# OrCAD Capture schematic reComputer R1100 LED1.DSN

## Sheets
1 02 LED: size A3; rev: v1.0
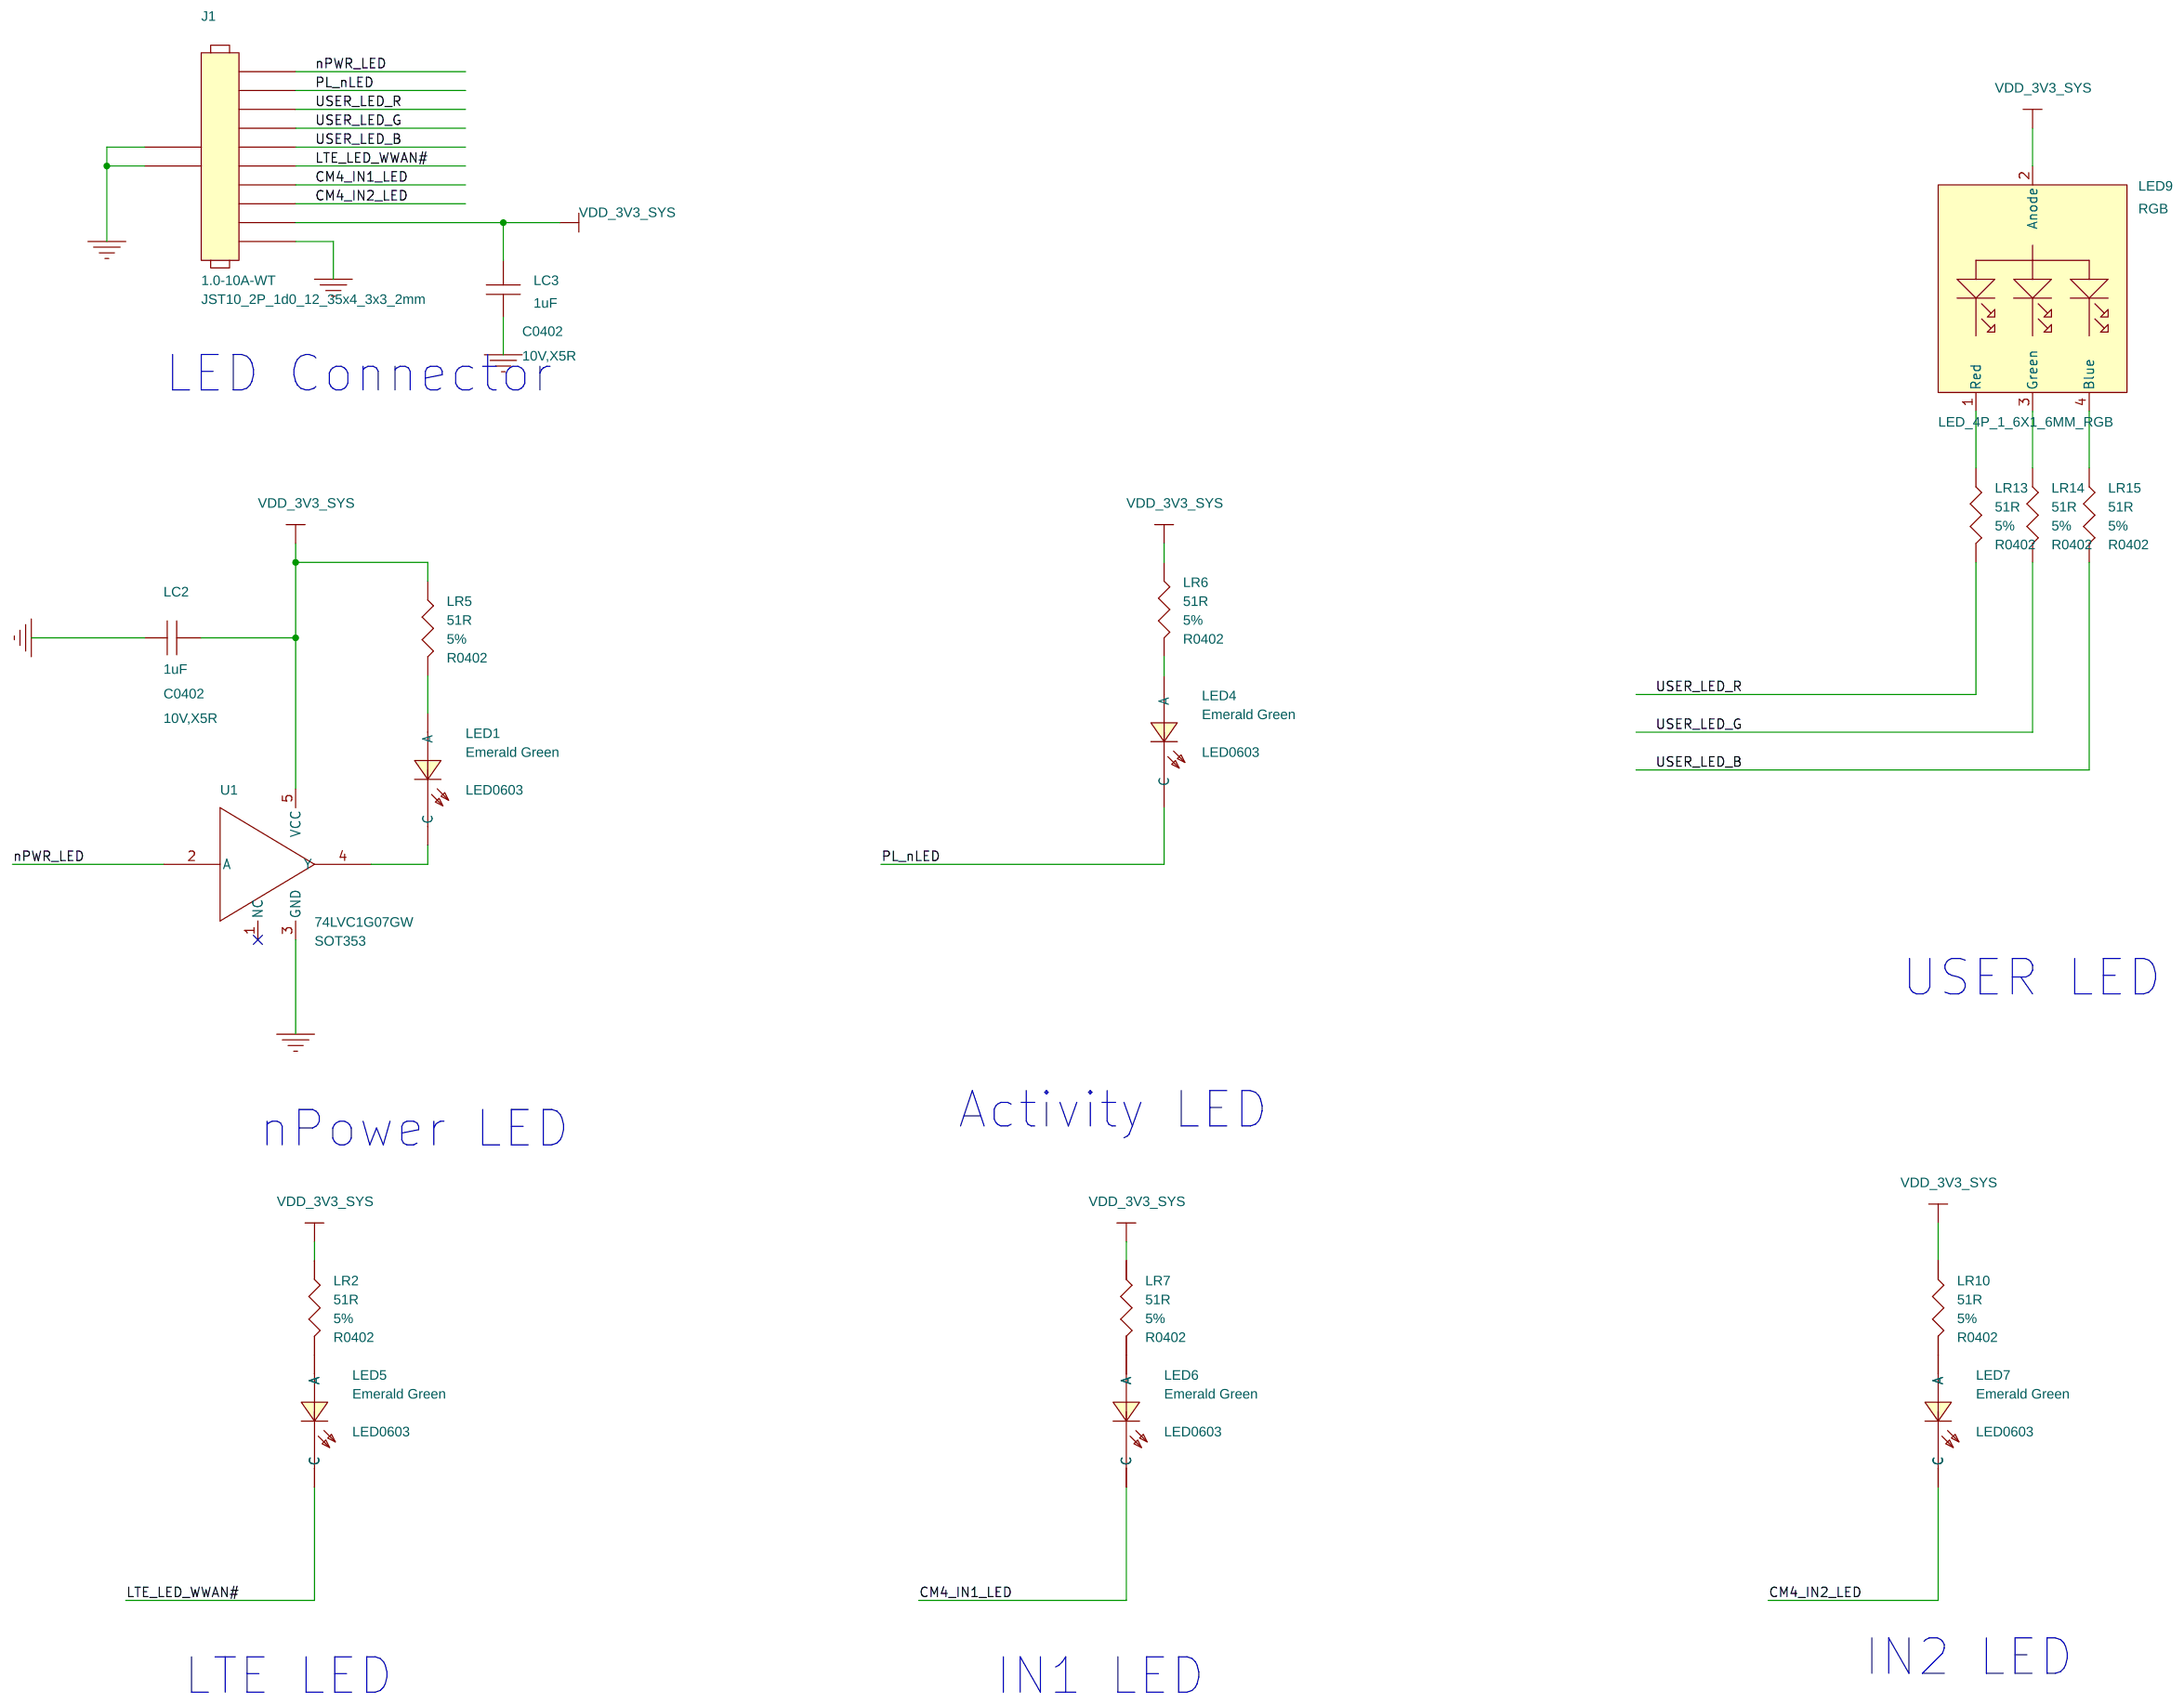
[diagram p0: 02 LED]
2 01 Title / Revision History
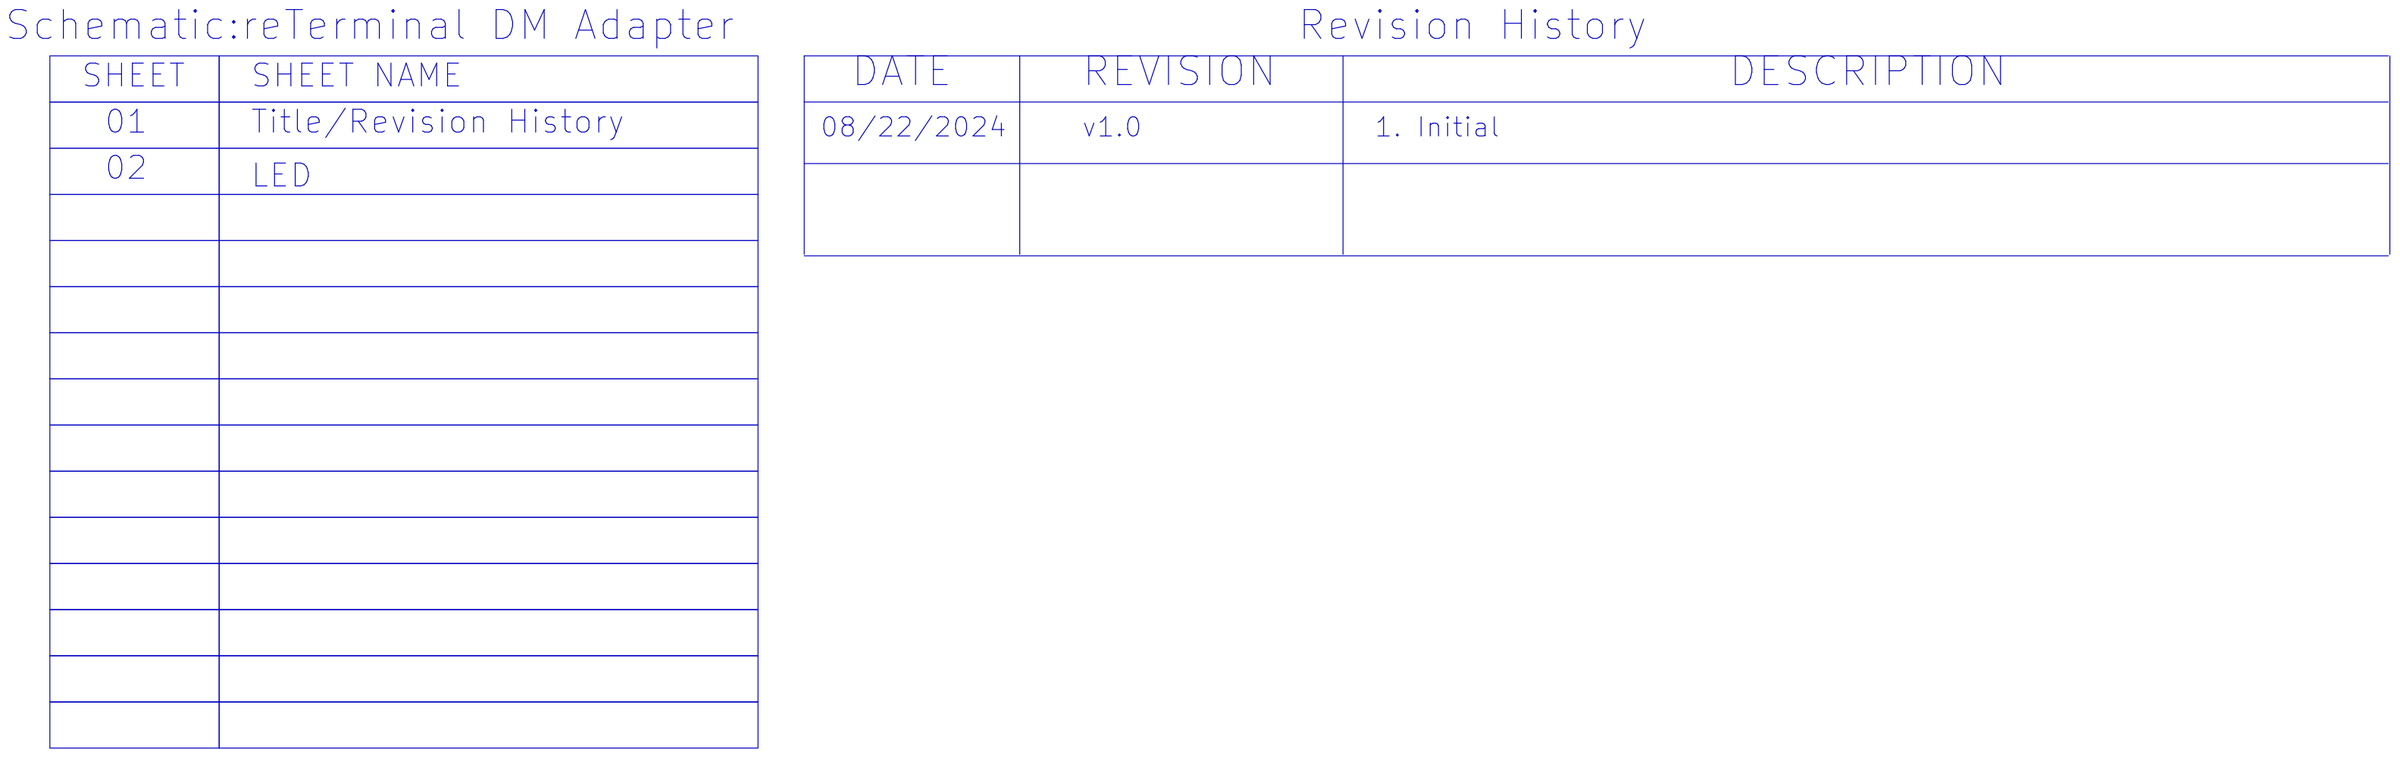
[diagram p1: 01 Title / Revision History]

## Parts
J1  1.0-10A-WT  [JST10_2P_1d0_12_35x4_3x3_2mm]
LC2  1uF  [C0402]
LC3  1uF  [C0402]
LED1  Emerald Green  [LED0603]
LED4  Emerald Green  [LED0603]
LED5  Emerald Green  [LED0603]
LED6  Emerald Green  [LED0603]
LED7  Emerald Green  [LED0603]
LED9  RGB  [LED_4P_1_6X1_6MM_RGB]
LR2  51R  [R0402]
LR5  51R  [R0402]
LR6  51R  [R0402]
LR7  51R  [R0402]
LR10  51R  [R0402]
LR13  51R  [R0402]
LR14  51R  [R0402]
LR15  51R  [R0402]
U1  74LVC1G07GW  [SOT353]

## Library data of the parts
J1 = JST_10+2P: SMD Male 1.0mm; 10P+2P-1.00mm; Manufacturer: 思拓展; PN: 320112081; Package Size: 1.0-10P; Status: reComputer R1002; Temperature: -25°C to 70°C
LC2 LC3 = CC: SMD CAP Ceramic 1uF-10V-10%-X5R;0402; Manufacturer: YAGEO; Manufacturer Part Number: CC0402KRX5R6BB105; PN: 302010040; Part Type: Ceramic; Rating: 10V,X5R; Status: BeagleBone Carrier Board; Temperature: -55°C to 85°C
LED1 LED4-LED7 = Single_LED: SMD LED Clear-Green;LED-0603; Manufacturer: Everlight; Manufacturer Part Number: 19-217/GHC-YR1S2/6T; PN: 304092047; Package Size: 0603; Status: ReComputer R1000; Temperature: -40°C to 85°C
LED9 = RGB_LED_19-237: SMD LED RGB;4P-1.6*1.6*0.35mm; Manufacturer: Everlight; Manufacturer Part Number: 19-237/R6GHBHC-D02/2T; PN: 304091807; Package Size: 1.6*1.6mm;4-SMD; Status: SenseCAP M2; Temperature: -40°C to 85°C
LR2 LR5-LR7 LR10 LR13-LR15 = R: SMD RES 51R-5%-1/16W;0402; Manufacturer: YAGEO; Manufacturer Part Number: RC0402JR-0751RL; PN: 301010080; Package Size: 0402; Rating: 5%; Temperature: -55°C to 155°C
U1 = SN74LVC1G07DCK: SMD IC Logic;TSSOP-5; Manufacturer: NXP; PN: 310050830; Part Type: Buffer; Status: ST; Temperature: -40°C to 125°C

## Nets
GND: J1.10 J1.S1 J1.S2 LC2.1 LC3.1 U1.3(GND)
VDD_3V3_SYS: J1.9 LC2.2 LC3.2 LED9.2(Anode) LR2.1 LR5.1 LR6.1 LR7.1 LR10.1 U1.5(VCC)
CM4_IN1_LED: J1.7 LED6.2(C)
CM4_IN2_LED: J1.8 LED7.2(C)
LTE_LED_WWAN#: J1.6 LED5.2(C)
nPWR_LED: J1.1 U1.2(A)
PL_nLED: J1.2 LED4.2(C)
USER_LED_B: J1.5 LR15.2
USER_LED_G: J1.4 LR14.2
USER_LED_R: J1.3 LR13.2
N19185: LED1.1(A) LR5.2
N19189: LED4.1(A) LR6.2
N19259: LED1.2(C) U1.4(Y)
N33927: LED5.1(A) LR2.2
N33969: LED6.1(A) LR7.2
N34011: LED7.1(A) LR10.2
N35488: LED9.1(Red) LR13.1
N35492: LED9.3(Green) LR14.1
N35496: LED9.4(Blue) LR15.1

Not connected (* = marked no-connect by the designer): U1 1(NC)*

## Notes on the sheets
sheet 1
- LED Connector
- USER LED
- Activity LED
- nPower LED
- IN2 LED
- LTE LED
- IN1 LED
sheet 2
- Schematic:reTerminal DM Adapter
- Revision History
- SHEET
- SHEET NAME
- DATE
- REVISION
- DESCRIPTION
- 01
- Title/Revision History
- 08/22/2024
- v1.0
- 1. Initial
- 02
- LED
